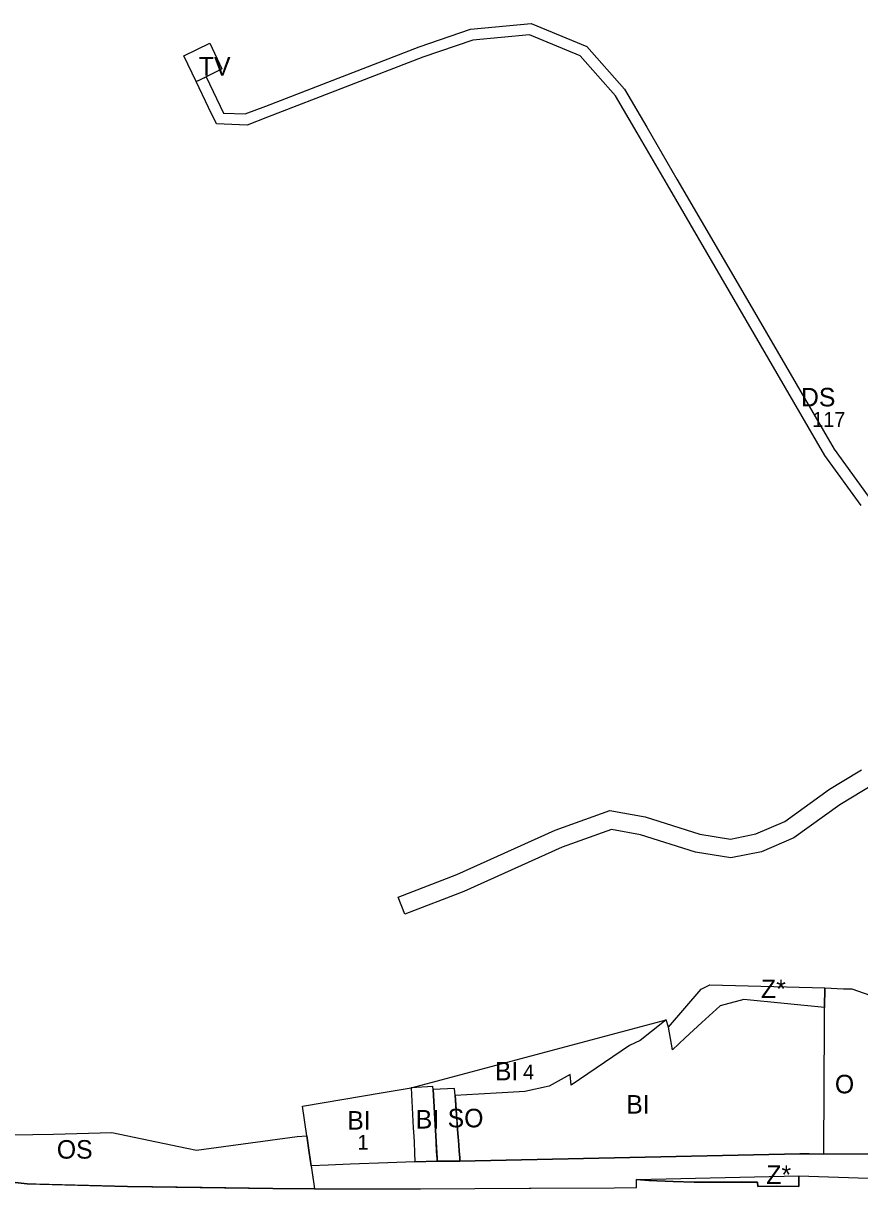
# Model space of a CAD drawing. Extents: x -521621 to -516769, y -1190068 to -1185078.
# Drawn here: x -519528 to -519076, y -1187168 to -1186538 of the extents above; entities that cross this region are included whole.
import ezdxf

# ---------------------------------------------------------------- set-up
doc = ezdxf.new("R2010")
doc.units = 0
for name, color, linetype in [('bydleni_n', 7, 'Continuous'), ('bydleni_s', 7, 'Continuous'), ('fpl_id', 7, 'Continuous'), ('s_zelen_s', 7, 'Continuous'), ('sm_vyuziti_s', 7, 'Continuous'), ('v_infrastr_n', 7, 'Continuous'), ('v_infrastr_s', 7, 'Continuous')]:
    doc.layers.add(name, color=color, linetype=linetype)

msp = doc.modelspace()

# ---------------------------------------------------------------- linework, layer by layer
at = {"layer": 'bydleni_n'}
for points in [[(-519243.91, -1187111.93), (-519257.18, -1187114.73), (-519269.34, -1187115.44), (-519282.06, -1187116.19), (-519294.77, -1187116.93), (-519295.05, -1187113.11), (-519306.63, -1187113.6), (-519306.72, -1187112.05), (-519318.38, -1187112.72), (-519180.77, -1187076), (-519188.69, -1187082.32), (-519194.92, -1187087.29), (-519200.56, -1187089.87), (-519232.12, -1187111.29), (-519232.7, -1187105.55)], [(-519374.79, -1187138.62), (-519377.12, -1187122.72), (-519333.59, -1187115.31), (-519318.38, -1187112.72), (-519317.33, -1187134.43), (-519316.98, -1187139.13), (-519316.76, -1187142.18), (-519316.6, -1187147.92), (-519316.47, -1187152.81), (-519331.04, -1187153.34), (-519351.35, -1187154.08), (-519363.32, -1187154.52), (-519372.41, -1187154.85), (-519372.42, -1187154.83), (-519373.47, -1187147.63)]]:
    msp.add_lwpolyline(points, close=True, dxfattribs=at)
at = {"layer": 'bydleni_s'}
msp.add_line((-519243.91, -1187111.93), (-519257.18, -1187114.73), dxfattribs=at)
for points in [[(-519138.88, -1187065.1), (-519151.79, -1187068.54)], [(-519095.65, -1187120.65), (-519095.47, -1187069.4), (-519138.88, -1187065.1)], [(-519151.79, -1187068.54), (-519161.61, -1187077.59)], [(-519180.77, -1187076), (-519188.69, -1187082.32)], [(-519179.53, -1187080.02), (-519180.77, -1187076)], [(-519177.52, -1187092.26), (-519179.53, -1187080.02)], [(-519161.61, -1187077.59), (-519170.58, -1187085.86)], [(-519188.69, -1187082.32), (-519194.92, -1187087.29)], [(-519170.58, -1187085.86), (-519177.52, -1187092.26)], [(-519200.56, -1187089.87), (-519232.12, -1187111.29)], [(-519194.92, -1187087.29), (-519200.56, -1187089.87)], [(-519232.7, -1187105.55), (-519243.91, -1187111.93)], [(-519232.12, -1187111.29), (-519232.7, -1187105.55)], [(-519305.2, -1187138.59), (-519305.36, -1187135.86), (-519306.26, -1187120.03), (-519306.63, -1187113.6), (-519306.72, -1187112.05), (-519318.38, -1187112.72)], [(-519318.38, -1187112.72), (-519317.33, -1187134.43), (-519316.98, -1187139.13)], [(-519282.06, -1187116.19), (-519294.77, -1187116.93)], [(-519294.77, -1187116.93), (-519294.59, -1187119.32)], [(-519269.34, -1187115.44), (-519282.06, -1187116.19)], [(-519257.18, -1187114.73), (-519269.34, -1187115.44)], [(-519294.59, -1187119.32), (-519293.41, -1187135.17)], [(-519107.05, -1187148.43), (-519103.69, -1187148.5), (-519095.75, -1187148.68), (-519095.71, -1187138.47), (-519095.7, -1187134.66), (-519095.67, -1187125.65), (-519095.65, -1187120.65)], [(-519293.41, -1187135.17), (-519293.08, -1187139.62), (-519292.97, -1187141.12)], [(-519316.98, -1187139.13), (-519316.76, -1187142.18)], [(-519316.76, -1187142.18), (-519316.6, -1187147.92)], [(-519305.01, -1187141.89), (-519305.2, -1187138.59)], [(-519304.71, -1187147.21), (-519305.01, -1187141.89)], [(-519292.97, -1187141.12), (-519292.56, -1187146.75)], [(-519316.6, -1187147.92), (-519316.47, -1187152.81), (-519304.41, -1187152.37), (-519304.49, -1187150.97), (-519304.71, -1187147.21)], [(-519292.56, -1187146.75), (-519292.28, -1187150.51)], [(-519292.14, -1187152.32), (-519108.66, -1187148.39)], [(-519108.66, -1187148.39), (-519107.05, -1187148.43)], [(-519292.28, -1187150.51), (-519292.19, -1187151.67), (-519292.14, -1187152.32)]]:
    msp.add_lwpolyline(points, dxfattribs=at)
at = {"layer": 's_zelen_s'}
for points in [[(-519179.53, -1187080.02), (-519161.95, -1187059.54), (-519157.33, -1187057.16), (-519095.24, -1187058.86), (-519095.47, -1187069.4), (-519138.88, -1187065.1), (-519151.79, -1187068.54), (-519161.61, -1187077.59), (-519170.58, -1187085.86), (-519177.52, -1187092.26)], [(-519196.86, -1187162.3), (-519109.24, -1187160.25), (-519109.24, -1187165.99), (-519121.09, -1187165.8), (-519131.35, -1187166.13), (-519131.52, -1187163.79), (-519142.49, -1187163.79), (-519153.04, -1187163.79), (-519165.75, -1187163.79), (-519177.13, -1187163.3), (-519190.24, -1187162.74)]]:
    msp.add_lwpolyline(points, close=True, dxfattribs=at)
at = {"layer": 'sm_vyuziti_s'}
for points in [[(-519294.77, -1187116.93), (-519295.05, -1187113.11), (-519306.63, -1187113.6), (-519306.26, -1187120.03)], [(-519294.59, -1187119.32), (-519294.77, -1187116.93)], [(-519306.26, -1187120.03), (-519305.36, -1187135.86)], [(-519293.41, -1187135.17), (-519293.69, -1187131.42), (-519294.33, -1187122.86), (-519294.59, -1187119.32)], [(-519305.36, -1187135.86), (-519305.2, -1187138.59), (-519305.01, -1187141.89), (-519304.49, -1187150.97), (-519304.41, -1187152.37), (-519292.14, -1187152.32), (-519292.19, -1187151.67), (-519292.28, -1187150.51), (-519292.56, -1187146.75), (-519292.97, -1187141.12), (-519293.08, -1187139.62), (-519293.41, -1187135.17)]]:
    msp.add_lwpolyline(points, dxfattribs=at)
at = {"layer": 'v_infrastr_n'}
for points in [[(-519075.63, -1186798.4), (-519095.14, -1186771.38), (-519142.19, -1186690.58), (-519180.2, -1186625.31), (-519196.55, -1186597.24), (-519208.18, -1186577.28), (-519227.21, -1186555.73), (-519254.63, -1186544.27), (-519285.21, -1186547.17), (-519312.1, -1186556.39), (-519395.93, -1186588.82), (-519407.03, -1186593.11), (-519423.55, -1186592.47), (-519427.77, -1186583.63), (-519434.47, -1186569.61), (-519429.06, -1186567.03), (-519419.69, -1186586.61), (-519408.04, -1186587.07), (-519396.94, -1186582.77), (-519314.15, -1186550.76), (-519286.48, -1186541.26), (-519253.7, -1186538.15), (-519223.63, -1186550.73), (-519203.29, -1186573.75), (-519191.37, -1186594.22), (-519175.02, -1186622.29), (-519137.01, -1186687.56), (-519090.1, -1186768.1), (-519071.8, -1186793.45)], [(-519068.5, -1186948.65), (-519087.09, -1186959.97), (-519111.91, -1186977.86), (-519129.46, -1186985.35), (-519145.9, -1186988.7), (-519165.02, -1186985.57), (-519194.65, -1186976.29), (-519210.41, -1186973.39), (-519237.02, -1186982.89), (-519290.02, -1187006.82), (-519321.89, -1187019.12), (-519325.49, -1187009.79), (-519293.88, -1186997.59), (-519240.76, -1186973.61), (-519211.24, -1186963.07), (-519192.24, -1186966.57), (-519162.71, -1186975.82), (-519146.1, -1186978.53), (-519132.45, -1186975.75), (-519116.86, -1186969.1), (-519092.62, -1186951.63), (-519085.78, -1186947.47), (-519075.41, -1186941.15)]]:
    msp.add_lwpolyline(points, dxfattribs=at)
at = {"layer": 'v_infrastr_s'}
for points in [[(-519434.47, -1186569.61), (-519441.16, -1186555.63), (-519427.17, -1186548.94), (-519420.58, -1186562.73), (-519421.13, -1186563.01), (-519422.63, -1186563.79), (-519424.14, -1186564.57), (-519426.6, -1186565.8), (-519429.06, -1186567.03), (-519433.48, -1186569.14)], [(-519095.75, -1187148.68), (-519095.71, -1187138.47), (-519095.7, -1187134.66), (-519095.67, -1187125.65), (-519095.65, -1187120.65), (-519095.47, -1187069.4), (-519095.24, -1187058.86), (-519085.06, -1187059.33), (-519080.57, -1187059.34), (-519053.94, -1187068.75), (-519053.58, -1187131.78), (-519053.53, -1187139.7), (-519053.48, -1187148.58)], [(-519471.58, -1187166.09), (-519520.78, -1187164.7), (-519525.62, -1187164.56), (-519568.17, -1187159.87), (-519565.59, -1187148.78), (-519570.28, -1187131.58), (-519542.51, -1187138.24), (-519533.88, -1187138.14), (-519511.41, -1187137.88), (-519479.95, -1187136.97), (-519439.45, -1187145.43), (-519434.32, -1187146.5), (-519379.97, -1187139), (-519374.79, -1187138.62), (-519373.47, -1187147.63), (-519370.95, -1187164.84), (-519370.6, -1187167.23), (-519393.07, -1187167.04), (-519431.2, -1187166.58)]]:
    msp.add_lwpolyline(points, close=True, dxfattribs=at)
for points in [[(-519108.66, -1187148.39), (-519292.14, -1187152.32), (-519304.41, -1187152.37), (-519316.47, -1187152.81)], [(-518922.71, -1187162.32), (-518942.32, -1187160.52), (-518945.16, -1187162.22), (-518954.04, -1187162.56), (-518982.68, -1187163.67), (-518984.47, -1187163.74), (-518983.9, -1187161.37), (-518993.51, -1187160.27), (-518996.16, -1187159.32), (-519012.07, -1187151.66), (-519018.82, -1187148.41), (-519026.03, -1187148.52), (-519032.92, -1187148.54), (-519040.56, -1187148.55), (-519044.71, -1187148.56), (-519053.48, -1187148.58), (-519095.75, -1187148.68), (-519103.69, -1187148.5), (-519107.05, -1187148.43), (-519108.66, -1187148.39)], [(-519363.32, -1187154.52), (-519372.41, -1187154.85)], [(-519372.41, -1187154.85), (-519370.95, -1187164.84)], [(-519351.35, -1187154.08), (-519363.32, -1187154.52)], [(-519331.04, -1187153.34), (-519351.35, -1187154.08)], [(-519316.47, -1187152.81), (-519331.04, -1187153.34)], [(-519568.17, -1187159.87), (-519525.62, -1187164.56)], [(-519370.95, -1187164.84), (-519370.6, -1187167.23), (-519358.14, -1187167.28), (-519313.49, -1187167.23), (-519254.77, -1187166.94), (-519253.76, -1187166.93), (-519208.86, -1187166.73), (-519196.86, -1187166.59), (-519196.86, -1187162.3)], [(-519196.86, -1187162.3), (-519109.24, -1187160.25)], [(-519196.86, -1187166.59), (-519196.86, -1187162.3), (-519190.24, -1187162.74), (-519177.13, -1187163.3), (-519165.75, -1187163.79), (-519153.04, -1187163.79), (-519142.49, -1187163.79), (-519131.52, -1187163.79), (-519131.35, -1187166.13)], [(-519109.24, -1187160.25), (-519007.58, -1187163.74), (-518983.81, -1187168.29), (-518901.11, -1187167.15), (-518901.2, -1187163.65)], [(-519109.24, -1187165.99), (-519109.24, -1187160.25)], [(-519109.24, -1187160.25), (-519007.58, -1187163.74)], [(-519525.62, -1187164.56), (-519471.58, -1187166.09)], [(-519471.58, -1187166.09), (-519393.07, -1187167.04)], [(-519393.07, -1187167.04), (-519370.6, -1187167.23)], [(-519370.6, -1187167.23), (-519358.14, -1187167.28)], [(-519358.14, -1187167.28), (-519313.49, -1187167.23)], [(-519313.49, -1187167.23), (-519254.77, -1187166.94)], [(-519254.77, -1187166.94), (-519253.76, -1187166.93)], [(-519253.76, -1187166.93), (-519208.86, -1187166.73)], [(-519208.86, -1187166.73), (-519196.86, -1187166.59)], [(-519131.35, -1187166.13), (-519121.09, -1187165.8)], [(-519121.09, -1187165.8), (-519109.24, -1187165.99)]]:
    msp.add_lwpolyline(points, dxfattribs=at)

# ---------------------------------------------------------------- texts
at = {"layer": 'bydleni_n'}
for p in [(-519273.28, -1187108.75), (-519352.95, -1187135.33)]:
    msp.add_text('BI', height=10, dxfattribs=at).set_placement(p)
at = {"layer": 'bydleni_s'}
for p in [(-519202.38, -1187126.69), (-519316, -1187134.75)]:
    msp.add_text('BI', height=10, dxfattribs=at).set_placement(p)
at = {"layer": 'fpl_id'}
for s, p in [('117', (-519102.02, -1186755.98)), ('4', (-519258.09, -1187108.2)), ('1', (-519347.43, -1187146.17))]:
    msp.add_text(s, height=8, dxfattribs=at).set_placement(p)
at = {"layer": 's_zelen_s'}
for p in [(-519129.65, -1187064.32), (-519126.78, -1187164.64)]:
    msp.add_text('Z*', height=10, dxfattribs=at).set_placement(p)
at = {"layer": 'sm_vyuziti_s'}
msp.add_text('SO', height=10, dxfattribs=at).set_placement((-519298.78, -1187134.11))
at = {"layer": 'v_infrastr_n'}
msp.add_text('DS', height=10, dxfattribs=at).set_placement((-519108.1, -1186744.94))
at = {"layer": 'v_infrastr_s'}
for s, p in [('TV', (-519433.03, -1186566.32)), ('O', (-519089.79, -1187115.75)), ('OS', (-519509.69, -1187151))]:
    msp.add_text(s, height=10, dxfattribs=at).set_placement(p)

doc.saveas('drawing.dxf')
